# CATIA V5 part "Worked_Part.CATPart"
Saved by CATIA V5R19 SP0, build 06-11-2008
Publications: "PunchBoundary1", "PunchBoundary2", "PunchBoundary3", "PunchBoundary4", "PunchBoundary5", "PunchBoundary6", "PunchBoundary7"
Bounding box of the stored display mesh (mm): x -45.182 to 851.192, y -88.967 to 51.033, z -2 to 0
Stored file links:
  C:\Documents and Settings\dpv\Desktop\SL9_test_14th_august\everything_done\Worked_Part.CATPart
  C:\Documents and Settings\dpv\Desktop\SL9_test_14th_august\Punch_sketches_done\Product1.CATProduct
  C:\Program Files\Dassault Systemes\Strip Layout Design\intel_a\resources\graphic\Template\StartingData.CATPart
  C:\Program Files\Dassault Systemes\Strip Layout Design\intel_a\resources\graphic\Template\Final_Part.CATPart
  C:\Documents and Settings\dpv\Desktop\SL9_test_14th_august\everything_done\Strip_Construction.CATPart
  C:\Documents and Settings\dpv\Desktop\SL9_test_14th_august\everything_done\Product1.CATProduct
  C:\Documents and Settings\dpv\Desktop\SL9_test_14th_august\everything_done\Part_for_Strip.CATPart
  C:\Program Files\Dassault Systemes\Strip Layout Design\intel_a\resources\graphic\Powercopies\PowerCopy_StripDefinition.CATPart
  \\dpv32plp\home\BPA_PRODUCTS\SL9\SL9_D6\Data\Starting Data\Part_for_strip_punches_contours.CATPart
  C:\Program Files\Dassault Systemes\Strip Layout Design\intel_a\resources\graphic\Powercopies\PowerCopy_PunchContour.CATPart
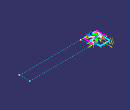
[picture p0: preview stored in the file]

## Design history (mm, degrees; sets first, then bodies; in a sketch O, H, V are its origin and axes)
Parameters
  Step_Length = 55 mm
  Number_Of_Steps = 12
  Strip_Width = 120 mm
  Rotation_Part = 60 deg
  Part_Thickness = 2 mm {= `External.Part Thickness`}
  Scrap_Area = 0.00288853 (area) {= area(Sketch4 )-area(Translate1 )}
  `%SCRAP` = 44 {= round(Scrap_Area /area(Sketch4)*100)}
External parameters (linked from other documents)
  External.Gx = 0 mm
  External.Gy = 0 mm
  External.Gz = 0 mm
  `External.Part Thickness` = 2 mm
SheetMetalParameters1: BendRadius 4, ReliefAxialLength 2, ReliefRadialLength 1, MinimumBendRadius 0, Thickness 2, KFactor 0.400515 {= log(min(100,max(20*SheetMetalParameters1.BendRadius,SheetMetalParameters1.Thickness)/SheetMetalParameters1.Thickness))/log(100)/2}
TTRSSet1
f4a2d38f3ddc11d3a929006094b99c4b_11 "CATTPSSet"
Set1
  Line1: linked copy from another document
  DatumCurve1 "Joint_Contours": linked copy from another document
Set2 "Stamp Contours"
  Rotate1: Axis Line1, Angle 60 {= Rotation_Part}, ToTransfor DatumCurve1
  Line2: linked copy from another document
Set3 "GS_COG"
  Point1: (0 {= External.Gx}, 0 {= External.Gy}, 0 {= External.Gz})
  Line3: type PtDir, Direction (0, 0, 1), Start 0, End 20, RefPoint Point1
  Point2: (1 {= Point1.X +1mm}, 0 {= Point1.Y}, 0 {= Point1.Z})
  Line4: type PtDir, Direction Line3, Start 0, End 20, RefPoint Point2
  Plane1: type 2Lines, Element1 Line4, Element2 Line3
  Sketch1 on Plane1, origin (0, 0, 0), H (-1, 0, 0), V (0, 0, 1)
    reference projected line E1 (0, 0) -> (0, 20) from Line3
    line L1 (0, 0) -> (-2.424, 2.4301)
    line L2 (-2.424, 2.4301) -> (-0.8757, 2.4301)
    line L3 (-0.8757, 2.4301) -> (-0.8757, 7.075)
    line L4 (-0.8757, 7.075) -> (0, 7.075)
    point P6 (0, 7.075)
    reference projected point E2 (0, 0) from Point1
    angle L2 L1 = 45.0724
    distance E1 L3 = 0.8757
    distance L2 L4 = 4.6449
    distance E2 L4 = 7.075
    horizontal: L2 H, L4 H
    vertical: L3 V
    coincidence: P6 E1
Set4 "Datas_For_Strip"
  Extract1 "MiseAPlat": ExtractElem face of Solid2
  Boundary1 "Boundary": Boundary Extract1
  Near1 "MainBoundary": ReferenceElement edge [face of Solid2 | face of Solid2], MultiElement Boundary1
  Plane2 "ReferencePlaneForSketches": type OffsetPt, RefPlane xy-plane, RefPoint vertex [element of Sketch4 | element of Sketch4]
Set5 "Strip_Definition"
  Set6 "OverAll_Boundary_Datas"
    Extremum1 "PointExtremum.Y+": Reference Near1, Direction2 Sketch5.H, Direction3 (0, 0, 1), Direction (0, 1, 0)
    Extremum2 "PointExtremum.Y-": Reference Near1, Direction2 Sketch5.H, Direction3 (0, 0, 1), Direction (0, 1, 0)
    Extremum3 "PointExtremum.X-": Reference Near1, Direction2 Sketch5.V, Direction3 (0, 0, 1), Direction (1, 0, 0)
    Translate1: Length 55 {= Step_Length}, Direction (1, 0, 0), ToTransfor Near1
    Extremum4 "PointExtremum.X+": Reference Translate1, Direction2 Sketch5.V, Direction3 (0, 0, 1), Direction (1, 0, 0)
    Sketch2 "OverAll_Boundary" on xy-plane, origin (0, 0, 0), H (1, 0, 0), V (0, 1, 0)
      line L1 (-45.1822, 38.1665) -> (107.5661, 38.1665)
      line L2 (107.5661, 38.1665) -> (107.5661, -76.1007)
      line L3 (107.5661, -76.1007) -> (-45.1822, -76.1007)
      line L4 (-45.1822, -76.1007) -> (-45.1822, 38.1665)
      reference projected point E1 (107.5661, 22.5665) from Extremum4
      reference projected point E2 (-0.3202, -76.1007) from Extremum2
      reference projected point E3 (41.4461, 38.1665) from Extremum1
      reference projected point E4 (-45.1822, -32.0913) from Extremum3
      horizontal: L1 H, L3 H
      vertical: L2 V, L4 V
      coincidence: L2 E1, L3 E2, L1 E3, L4 E4
  Set7 "Strip_Skeleton"
    Sketch3 "Boundary2Steps" on xy-plane, origin (0, 0, 0), H (1, 0, 0), V (0, 1, 0)
      line L1 (-23.808, 41.0329) -> (86.192, 41.0329)
      line L2 (86.192, 41.0329) -> (86.192, -78.9671)
      line L3 (86.192, -78.9671) -> (-23.808, -78.9671)
      line L4 (-23.808, -78.9671) -> (-23.808, 41.0329)
      reference projected line E1 (107.5661, 38.1665) -> (-45.1822, 38.1665) from Sketch2.L1
      reference projected line E2 (-45.1822, -76.1007) -> (107.5661, -76.1007) from Sketch2.L3
      reference projected line E3 (-45.1822, 38.1665) -> (-45.1822, -76.1007) from Sketch2.L4
      reference projected line E4 (107.5661, -76.1007) -> (107.5661, 38.1665) from Sketch2.L2
      construction line L5 (-70.2888, -18.9671) -> (96.3725, -18.9671)
      reference projected line E5 (107.5661, 38.1665) -> (-45.1822, 38.1665) from Sketch2.L1
      reference projected line E6 (-45.1822, -76.1007) -> (107.5661, -76.1007) from Sketch2.L3
      axis line L6 (31.192, -92.2122) -> (31.192, 51.3206)
      reference projected line E7 (107.5661, -76.1007) -> (107.5661, 38.1665) from Sketch2.L2
      reference projected line E8 (-45.1822, 38.1665) -> (-45.1822, -76.1007) from Sketch2.L4
      length L2 = 120 {= Strip_Width}
      length L1 = 110 {= 2*Step_Length}
      distance E1 E2 = 114.2673 (reference)
      distance E3 E4 = 152.7482 (reference)
      horizontal: L1 H, L3 H, L5 H
      vertical: L2 V, L4 V, L6 V
      symmetry: E5 E6 L5, L3 L1 L5, E7 E8 L6, L4 L2 L6
    Sketch4 "Boundary1Step" on xy-plane, origin (0, 0, 0), H (1, 0, 0), V (0, 1, 0)
      point P1 (-23.808, 41.0329)
      line L1 (-23.808, 41.0329) -> (31.192, 41.0329)
      line L2 (31.192, 41.0329) -> (31.192, -78.9671)
      line L3 (31.192, -78.9671) -> (-23.808, -78.9671)
      line L4 (-23.808, -78.9671) -> (-23.808, 41.0329)
      reference projected point E1 (-23.808, 41.0329) from vertex [element of Sketch3 | element of Sketch3]
      length L1 = 55 {= Step_Length}
      length L2 = 120 {= Strip_Width}
      horizontal: L1 H, L3 H
      vertical: L2 V, L4 V
      coincidence: P1 E1
    Sketch5 "BoundaryStrip" on xy-plane, origin (0, 0, 0), H (1, 0, 0), V (0, 1, 0)
      line L1 (136.192, 41.0329) -> (851.192, 41.0329)
      line L2 (851.192, 41.0329) -> (851.192, -78.9671)
      line L3 (851.192, -78.9671) -> (136.192, -78.9671)
      line L4 (136.192, -78.9671) -> (136.192, 41.0329)
      reference projected line E1 (86.192, 41.0329) -> (-23.808, 41.0329) from Sketch3.L1
      reference projected line E2 (86.192, -78.9671) -> (86.192, 41.0329) from Sketch3.L2
      length L1 = 715 {= Step_Length * (Number_Of_Steps + 1)}
      length L2 = 120 {= Strip_Width}
      distance E2 L4 = 50
      horizontal: L1 H, L3 H
      vertical: L2 V, L4 V
      coincidence: L1 E1
    Extract2: ExtractElem Sketch4.L2
  Set8 "Punches_Construction"
    Set9 "Sketch_Punches"
      Sketch6 on Plane2, origin (0, 0, 0), H (1, 0, 0), V (0, 1, 0)
        circle A1 centre (0, -65.2237) radius 5.1261
        point P1 (0, -65.2237)
        coincidence: P1 V
      Sketch7 on Plane2, origin (0, 0, 0), H (1, 0, 0), V (0, 1, 0)
        circle A1 centre (43.5734, 23.4864) radius 4.7174
      Sketch8 on Plane2, origin (0, 0, 0), H (1, 0, 0), V (0, 1, 0)
        line L1 (25.9763, -13.7108) -> (-23.4821, -13.7108)
        line L2 (-23.4821, -13.7108) -> (-23.4821, -31.2218)
        line L3 (-23.4821, -31.2218) -> (25.9763, -31.2218)
        line L4 (25.9763, -31.2218) -> (25.9763, -13.7108)
        horizontal: L1 H, L3 H
        vertical: L2 V, L4 V
      Sketch9 on Plane2, origin (0, 0, 0), H (1, 0, 0), V (0, 1, 0)
        line L1 (29.7251, -30.9218) -> (-26.9679, -30.9218)
        line L2 (-26.9679, -30.9218) -> (-0.5287, -64.1475)
        line L3 (-0.5287, -64.1475) -> (-0.5287, -83.9671)
        line L4 (4.4713, -88.9671) -> (50.6382, -88.9671)
        line L5 (55.6382, -83.9671) -> (55.6382, -67.007)
        line L6 (55.6382, -67.007) -> (29.7251, -30.9218)
        reference projected line E1 (-23.4821, -31.2218) -> (25.9763, -31.2218) from Sketch8.L3
        arc A1 centre (50.6382, -83.9671) radius 5 from (55.6382, -83.9671) to (50.6382, -88.9671) cw
        arc A2 centre (4.4713, -83.9671) radius 5 from (-0.5287, -83.9671) to (4.4713, -88.9671) ccw
        distance L1 E1 = 0.3
        radius A1 = 5
        radius A2 = 5
        horizontal: L1 H, L4 H
        vertical: L3 V, L5 V
        tangency: A1 L5, A1 L4, A2 L3, A2 L4
      Sketch10 on Plane2, origin (0, 0, 0), H (1, 0, 0), V (0, 1, 0)
        line L1 (27.4232, -14.0108) -> (-4.8037, -14.0108)
        line L2 (-4.8037, -14.0108) -> (42.6816, 17.805)
        line L3 (42.6816, 17.805) -> (48.0592, 9.779)
        line L4 (48.0592, 9.779) -> (27.4232, -14.0108)
        reference projected line E1 (25.9763, -13.7108) -> (-23.4821, -13.7108) from Sketch8.L1
        distance L1 E1 = 0.3
        horizontal: L1 H
        perpendicularity: L3 L2
      Sketch11 on Plane2, origin (0, 0, 0), H (1, 0, 0), V (0, 1, 0)
        line L1 (49.751, 6.7151) -> (43.5882, 15.913)
        line L2 (43.5882, 15.913) -> (41.1957, 34.0406)
        line L3 (41.1957, 34.0406) -> (41.1957, 46.0329)
        line L4 (46.1957, 51.0329) -> (92.5694, 51.0329)
        line L5 (97.5694, 46.0329) -> (97.5694, 27.7649)
        line L6 (97.5694, 27.7649) -> (49.751, 6.7151)
        reference projected line E1 (48.0592, 9.779) -> (42.6816, 17.805) from Sketch10.L3
        arc A1 centre (92.5694, 46.0329) radius 5 from (97.5694, 46.0329) to (92.5694, 51.0329) ccw
        arc A2 centre (46.1957, 46.0329) radius 5 from (46.1957, 51.0329) to (41.1957, 46.0329) ccw
        distance L1 E1 = 0.3
        radius A1 = 5
        radius A2 = 5
        vertical: L3 V, L5 V
        horizontal: L4 H
        tangency: A1 L5, A1 L4, A2 L4, A2 L3
      Sketch12 on Plane2, origin (31.192, 41.0329, 0), H (1, 0, 0), V (0, 1, 0)
        circle A1 centre (-12.4427, -24.5131) radius 3.8991
    Set10 "Cutting_Shapes"
      Fill1 "Fill.Main": Boundary Near1
      Fill2 "Fill.Trans": Boundary Translate1
      Extrude1 "Extrude.Main": Lim1 3 {= 1.5*Part_Thickness}, Lim2 3 {= 1.5*Part_Thickness}, Element1 Fill1, Direction (0, 0, 1)
      Extrude2 "Extrude.Trans": Lim1 3 {= 1.5*Part_Thickness}, Lim2 3 {= 1.5*Part_Thickness}, Element1 Fill2, Direction (0, 0, 1)
      Join1 "Cutting_2_Parts": Elements (Extrude1; Extrude2)
    Set11 "Punch"
      Split1 "SurfacePunch": ToCut Fill3, Cutting Join1
      Boundary2 "PunchBoundary": Boundary Split1
      Fill3 "Fill.Sketch": Boundary Sketch11
    Set12 "Punch"
      Split2 "SurfacePunch": ToCut Fill4, Cutting Join1
      Boundary3 "PunchBoundary": Boundary Split2
      Fill4 "Fill.Sketch": Boundary Sketch10
    Set13 "Punch"
      Split3 "SurfacePunch": ToCut Fill5, Cutting Join1
      Boundary4 "PunchBoundary": Boundary Split3
      Fill5 "Fill.Sketch": Boundary Sketch8
    Set14 "Punch"
      Split4 "SurfacePunch": ToCut Fill6, Cutting Join1
      Boundary5 "PunchBoundary": Boundary Split4
      Fill6 "Fill.Sketch": Boundary Sketch9
    Set15 "Punch"
      Split5 "SurfacePunch": ToCut Fill7, Cutting Boundary1
      Boundary6 "PunchBoundary": Boundary Split5
      Fill7 "Fill.Sketch": Boundary Sketch7
    Set16 "Punch"
      Split6 "SurfacePunch": ToCut Fill8, Cutting Boundary1
      Boundary7 "PunchBoundary": Boundary Split6
      Fill8 "Fill.Sketch": Boundary Sketch12
    Set17 "Punch"
      Split7 "SurfacePunch": ToCut Fill9, Cutting Boundary1
      Boundary8 "PunchBoundary": Boundary Split7
      Fill9 "Fill.Sketch": Boundary Sketch6
  Point3 "Point_2Steps_CuttingLine": type OnCurve, Support Extract2, Ratio 0.5
  Sketch13 "2Steps_CuttingLine" on Plane2, origin (0, 0, 0), H (1, 0, 0), V (0, 1, 0)
    line L1 (16.0792, -65.3122) -> (13.5924, -78.9671)
    point P2 (13.5924, -78.9671)
    line L2 (16.0792, -65.3122) -> (-8.389, -25.3641)
    line L3 (-8.389, -25.3641) -> (28.9193, 0.8787)
    line L4 (28.9193, 0.8787) -> (62.9818, 22.5841)
    line L5 (62.9818, 22.5841) -> (51.9142, 41.0329)
    point P6 (51.9142, 41.0329)
    reference projected line E1 (-23.808, -78.9671) -> (31.192, -78.9671) from Sketch4.L3
    reference projected line E2 (86.192, 41.0329) -> (-23.808, 41.0329) from Sketch3.L1
    coincidence: P2 E1, P6 E2
Body1 (main body)
  Solid1: linked copy from another document
Body2 "Temporary_Body"
Body3 "COG"
  Shaft1: profile Sketch1, axis , angle 360
Body4 "NewBody"
  Solid2: CATSmSolid_Thickness 2, linked copy from another document
  Rotate2: Axis Line2, Angle 60 {= Rotation_Part}
  SHMMapping1: CATSHMMappingObject Rotate1, CATSHMMappingContext Rotate2
  Fill10: Boundary SHMMapping1
Relations
  rule "Rule_Angle_Sketch_Green":
    /*Rule created by asi 13/09/2005*/
    if Rotation_Part ==0deg
    deleted_Boolean = false
    else
    deleted_Boolean = true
